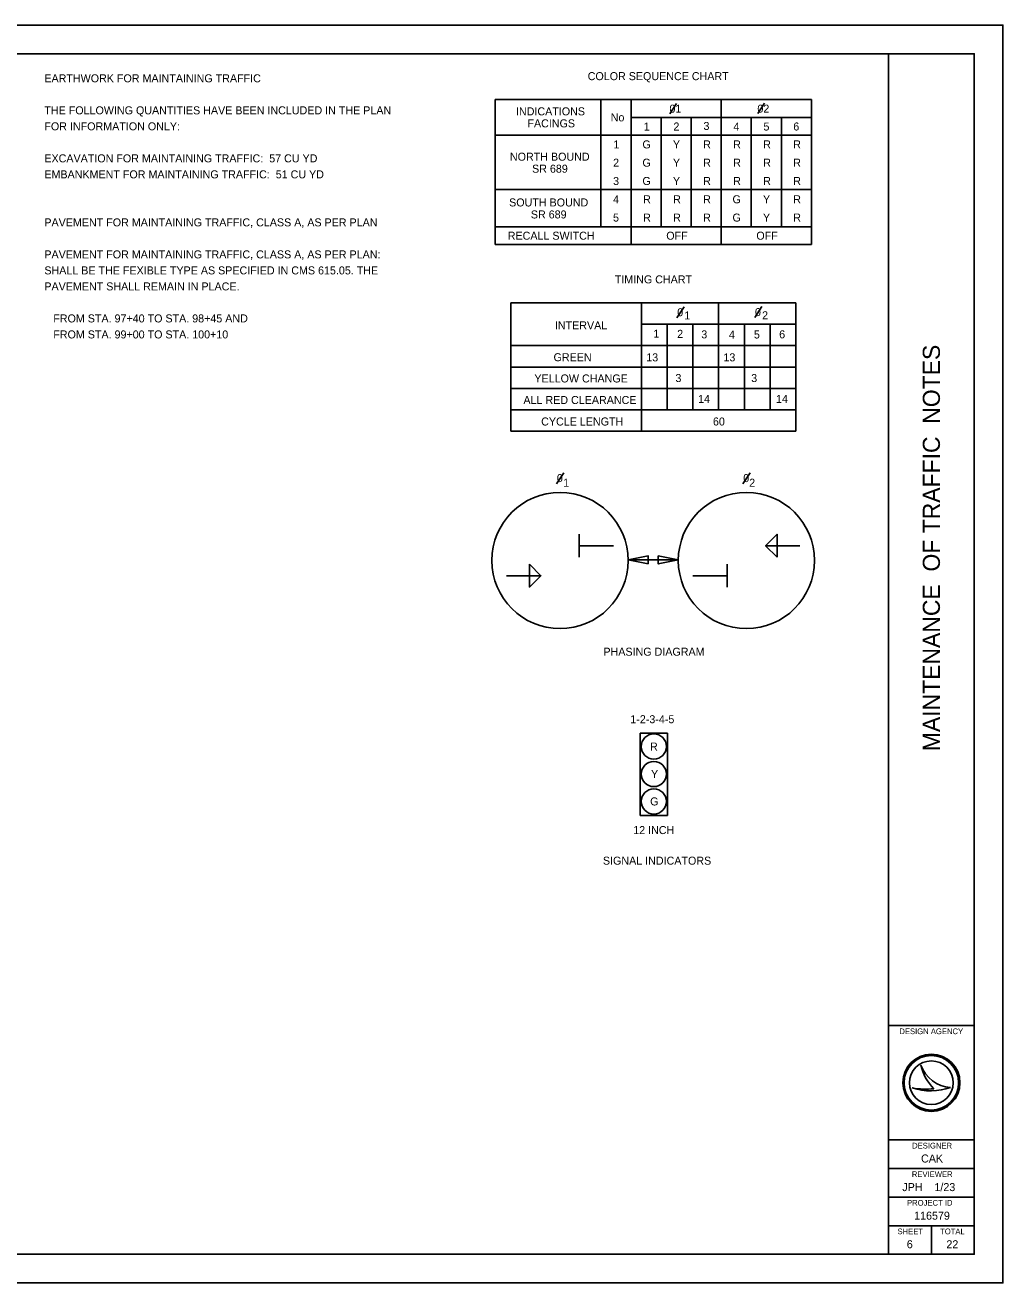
# Model space of a CAD drawing. Extents: x -1.9 to 59.7, y -1.6 to 50.3.
# Drawn here: x 16.9 to 34, y 0 to 22 of the extents above; entities that cross this region are included whole.
import ezdxf

# ---------------------------------------------------------------- set-up
doc = ezdxf.new("R2010")
doc.units = 0
for name, color, linetype in [('Default', 7, 'Continuous'), ('SG_P_Heads', 7, 'Continuous'), ('SH_Border', 7, 'Continuous'), ('SH_Cut_Line', 7, 'Continuous'), ('SH_Data', 7, 'Continuous'), ('SH_Text', 7, 'Continuous'), ('TX_P_1', 7, 'Continuous')]:
    doc.layers.add(name, color=color, linetype=linetype)

msp = doc.modelspace()

# ---------------------------------------------------------------- linework, layer by layer
at = {"layer": 'Default'}
for p, q in [((25.122, 20.699), (25.122, 18.162)), ((25.122, 20.699), (30.652, 20.699)), ((26.972, 20.699), (26.972, 18.474)), ((27.502, 20.699), (27.502, 18.162)), ((29.077, 20.699), (29.077, 18.162)), ((30.652, 20.699), (30.652, 18.512)), ((30.652, 20.699), (30.652, 18.162)), ((27.502, 20.387), (30.652, 20.387)), ((28.027, 20.387), (28.027, 18.474)), ((28.552, 20.387), (28.552, 18.474)), ((29.602, 20.387), (29.602, 18.474)), ((30.127, 20.387), (30.127, 18.474)), ((25.122, 20.074), (30.652, 20.074)), ((25.122, 19.127), (30.652, 19.127)), ((25.122, 18.474), (30.652, 18.474)), ((25.122, 18.162), (30.652, 18.162)), ((25.394, 17.145), (30.38, 17.145)), ((25.394, 17.145), (25.394, 14.895)), ((27.68, 17.145), (27.68, 14.895)), ((29.03, 17.145), (29.03, 15.27)), ((30.38, 17.145), (30.38, 14.895)), ((27.68, 16.77), (30.38, 16.77)), ((28.13, 16.77), (28.13, 15.27)), ((28.58, 16.77), (28.58, 15.27)), ((29.48, 16.77), (29.48, 15.27)), ((29.93, 16.77), (29.93, 15.27)), ((25.394, 16.395), (30.38, 16.395)), ((25.394, 16.02), (30.38, 16.02)), ((25.394, 15.645), (30.38, 15.645)), ((25.394, 15.27), (30.38, 15.27)), ((25.394, 14.895), (30.38, 14.895)), ((28.138, 9.617), (27.659, 9.617)), ((27.659, 9.617), (27.659, 8.175)), ((28.138, 8.175), (28.138, 9.617)), ((27.659, 8.175), (28.138, 8.175))]:
    msp.add_line(p, q, dxfattribs=at)
for centre in [(27.897, 9.381), (27.897, 8.9), (27.897, 8.421)]:
    msp.add_circle(centre, 0.22, dxfattribs=at)
at = {"layer": 'SG_P_Heads'}
for p, q in [((26.593, 13.096), (26.593, 12.696)), ((27.193, 12.895), (26.593, 12.895)), ((30.452, 12.895), (29.852, 12.895)), ((29.182, 12.17), (29.182, 12.57)), ((25.322, 12.37), (25.923, 12.37)), ((28.581, 12.37), (29.182, 12.37))]:
    msp.add_line(p, q, dxfattribs=at)
for points in [[(30.052, 12.695), (29.852, 12.895), (30.052, 13.095)], [(25.723, 12.57), (25.923, 12.37), (25.723, 12.17)], [(27.8, 12.575), (27.45, 12.645), (27.8, 12.715)], [(27.974, 12.715), (28.324, 12.645), (27.974, 12.575)]]:
    msp.add_lwpolyline(points, close=True, dxfattribs=at)
at = {"layer": 'SH_Border'}
for p, q in [((32, 0.5), (32, 21.5)), ((32, 4.5), (33.5, 4.5)), ((32, 2.5), (33.5, 2.5)), ((32, 2), (33.5, 2)), ((32, 1.5), (33.5, 1.5)), ((32, 1), (33.5, 1))]:
    msp.add_line(p, q, dxfattribs=at)
msp.add_lwpolyline([(1.5, 21.5), (33.5, 21.5), (33.5, 0.5), (1.5, 0.5)], close=True, dxfattribs=at)
at = {"layer": 'SH_Cut_Line'}
msp.add_lwpolyline([(0, 0), (34, 0), (34, 22), (0, 22)], close=True, dxfattribs=at)
at = {"layer": 'SH_Data'}
for p, q in [((28.324, 12.645), (27.45, 12.645)), ((32.567, 3.81), (32.567, 3.81)), ((32.417, 3.41), (32.417, 3.41)), ((32.75, 3.5), (32.75, 3.5)), ((33.087, 3.419), (33.087, 3.419)), ((32.75, 0.5), (32.75, 1))]:
    msp.add_line(p, q, dxfattribs=at)
for centre, radius in [((26.257, 12.636), 1.191), ((29.516, 12.636), 1.191), ((32.75, 3.5), 0.5), ((32.75, 3.5), 0.477), ((32.75, 3.5), 0.477), ((32.75, 3.5), 0.382)]:
    msp.add_circle(centre, radius, dxfattribs=at)
for centre, radius, start, end in [((33.116, 3.998), 0.58, 198.9257, 198.9319), ((33.347, 3.97), 0.796, 191.6379, 191.6421), ((33.116, 3.998), 0.58, 198.9319, 267.1657), ((33.347, 3.97), 0.796, 191.6421, 226.0947), ((32.739, 4.37), 1.013, 251.4576, 290.0832), ((32.648, 4.654), 1.266, 259.4964, 259.4995), ((32.739, 4.37), 1.013, 251.4527, 251.4576), ((32.648, 4.654), 1.266, 259.4995, 276.6672)]:
    msp.add_arc(centre, radius, start, end, dxfattribs=at)
at = {"layer": 'TX_P_1'}
for p, q in [((28.176, 20.45), (28.291, 20.631)), ((29.715, 20.456), (29.831, 20.637)), ((28.425, 17.074), (28.3, 16.882)), ((29.788, 17.078), (29.663, 16.885)), ((26.322, 14.169), (26.196, 13.977)), ((29.581, 14.169), (29.455, 13.977))]:
    msp.add_line(p, q, dxfattribs=at)

# ---------------------------------------------------------------- texts
at = {"layer": 'Default'}
for s, p in [('COLOR SEQUENCE CHART', (26.741, 21.038)), ('TIMING CHART', (27.214, 17.483)), ('R', (27.83, 9.311)), ('Y', (27.849, 8.831)), ('G', (27.833, 8.351)), ('SIGNAL INDICATORS', (27.007, 7.315))]:
    msp.add_text(s, height=0.14, dxfattribs=at).set_placement(p)
at = {"layer": 'SH_Data'}
msp.add_text('MAINTENANCE  OF TRAFFIC  NOTES', height=0.3, rotation=90, dxfattribs=at).set_placement((32.9, 9.3))
for s, height, p in [('0', 0.14, (26.202, 14.007)), ('DESIGN AGENCY', 0.1, (32.191, 4.35)), ('DESIGNER', 0.1, (32.414, 2.35)), ('CAK', 0.14, (32.57, 2.105)), ('REVIEWER', 0.1, (32.409, 1.85)), ('JPH    1/23', 0.14, (32.242, 1.605)), ('PROJECT ID', 0.1, (32.325, 1.35)), ('116579', 0.14, (32.449, 1.105)), ('SHEET', 0.1, (32.158, 0.85)), ('TOTAL', 0.1, (32.903, 0.85)), ('6', 0.14, (32.321, 0.605)), ('22', 0.14, (33.013, 0.605))]:
    msp.add_text(s, height=height, dxfattribs=at).set_placement(p)
at = {"layer": 'SH_Text'}
for s, p in [('EARTHWORK FOR MAINTAINING TRAFFIC', (17.24, 21)), ('THE FOLLOWING QUANTITIES HAVE BEEN INCLUDED IN THE PLAN ', (17.24, 20.44)), ('FOR INFORMATION ONLY:', (17.24, 20.16)), ('EXCAVATION FOR MAINTAINING TRAFFIC:  57 CU YD', (17.24, 19.6)), ('EMBANKMENT FOR MAINTAINING TRAFFIC:  51 CU YD', (17.24, 19.32)), ('PAVEMENT FOR MAINTAINING TRAFFIC, CLASS A, AS PER PLAN', (17.24, 18.48)), ('PAVEMENT FOR MAINTAINING TRAFFIC, CLASS A, AS PER PLAN:', (17.24, 17.92)), ('SHALL BE THE FEXIBLE TYPE AS SPECIFIED IN CMS 615.05. THE', (17.24, 17.64)), ('PAVEMENT SHALL REMAIN IN PLACE.', (17.24, 17.36)), ('   FROM STA. 97+40 TO STA. 98+45 AND', (17.24, 16.8)), ('   FROM STA. 99+00 TO STA. 100+10', (17.24, 16.52))]:
    msp.add_text(s, height=0.14, dxfattribs=at).set_placement(p)
at = {"layer": 'TX_P_1'}
for s, p in [('INDICATIONS', (25.487, 20.422)), ('01', (28.17, 20.469)), ('02', (29.708, 20.469)), ('FACINGS', (25.687, 20.212)), ('No', (27.143, 20.317)), ('1', (27.721, 20.157)), ('2', (28.24, 20.157)), ('3', (28.765, 20.167)), ('4', (29.29, 20.157)), ('5', (29.814, 20.157)), ('6', (30.336, 20.157)), ('1', (27.191, 19.844)), ('G', (27.698, 19.844)), ('Y', (28.231, 19.844)), ('R', (28.76, 19.844)), ('R', (29.285, 19.844)), ('R', (29.81, 19.844)), ('R', (30.335, 19.844)), ('NORTH BOUND', (25.381, 19.629)), ('2', (27.185, 19.524)), ('G', (27.698, 19.524)), ('Y', (28.231, 19.524)), ('R', (28.76, 19.524)), ('R', (29.285, 19.524)), ('R', (29.81, 19.524)), ('R', (30.335, 19.524)), ('SR 689', (25.768, 19.419)), ('3', (27.185, 19.204)), ('G', (27.698, 19.204)), ('Y', (28.231, 19.204)), ('R', (28.76, 19.204)), ('R', (29.285, 19.204)), ('R', (29.81, 19.204)), ('R', (30.335, 19.204)), ('SOUTH BOUND', (25.367, 18.829)), ('4', (27.185, 18.884)), ('R', (27.71, 18.884)), ('R', (28.235, 18.884)), ('R', (28.76, 18.884)), ('G', (29.273, 18.884)), ('Y', (29.806, 18.884)), ('R', (30.335, 18.884)), ('SR 689', (25.747, 18.619)), ('5', (27.184, 18.564)), ('R', (27.71, 18.564)), ('R', (28.235, 18.564)), ('R', (28.76, 18.564)), ('G', (29.273, 18.564)), ('Y', (29.806, 18.564)), ('R', (30.335, 18.564)), ('RECALL SWITCH', (25.343, 18.247)), ('OFF', (28.115, 18.247)), ('OFF', (29.69, 18.247)), ('0', (28.307, 16.908)), ('1', (28.429, 16.852)), ('0', (29.666, 16.911)), ('2', (29.791, 16.855)), ('INTERVAL ', (26.167, 16.679)), ('1', (27.889, 16.533)), ('2', (28.306, 16.53)), ('3', (28.727, 16.521)), ('4', (29.21, 16.517)), ('5', (29.647, 16.519)), ('6', (30.089, 16.522)), (' GREEN', (26.092, 16.121)), ('13', (27.765, 16.119)), ('13', (29.114, 16.119)), ('YELLOW CHANGE', (25.809, 15.75)), ('3', (28.275, 15.757)), ('3', (29.6, 15.757)), ('ALL RED CLEARANCE', (25.617, 15.373)), ('14', (28.671, 15.392)), ('14', (30.033, 15.392)), ('CYCLE LENGTH', (25.927, 14.997)), ('60', (28.931, 14.997)), ('0', (29.461, 14.007)), ('1', (26.312, 13.926)), ('2', (29.565, 13.926)), ('PHASING DIAGRAM', (27.016, 10.97)), ('1-2-3-4-5', (27.486, 9.789)), ('12 INCH', (27.537, 7.85))]:
    msp.add_text(s, height=0.14, dxfattribs=at).set_placement(p)

doc.saveas('drawing.dxf')
